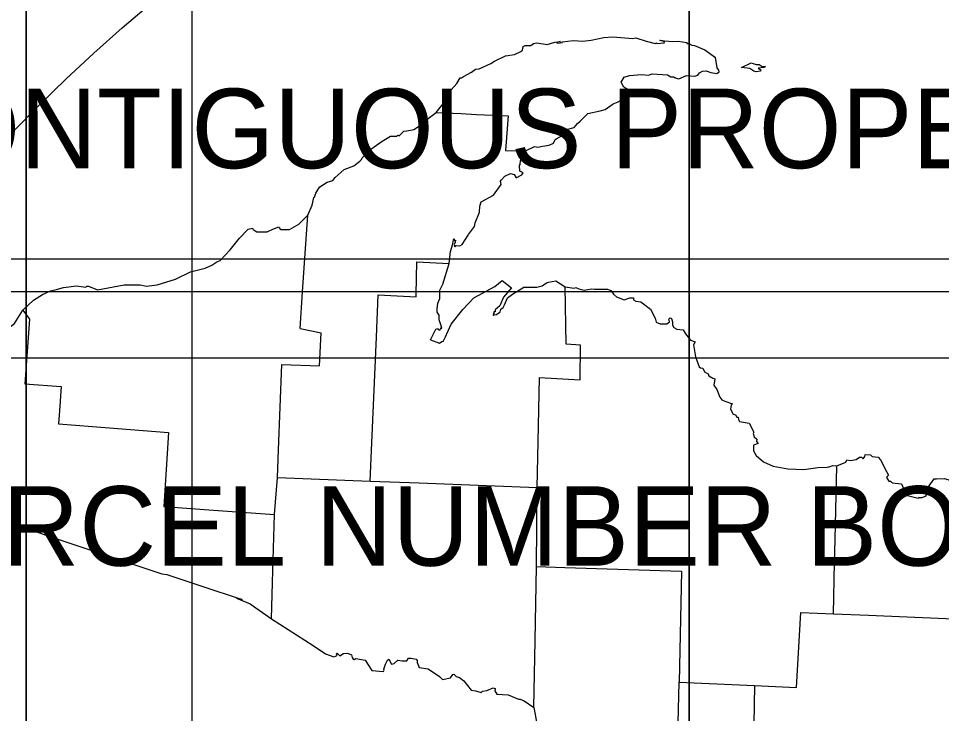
# Model space of a CAD drawing. Extents: x 2146475 to 2147951, y 2147003 to 2148003.
# Drawn here: x 2147652.9 to 2147708.6, y 2147835.5 to 2147877.5 of the extents above; entities that cross this region are included whole.
import ezdxf

# ---------------------------------------------------------------- set-up
doc = ezdxf.new("R2010")
doc.units = 0
for name, color, linetype in [('Sheet_Border_Prof3_Grid+Sta+EL_04_040+08_080', 7, 'Continuous'), ('Sheet_Border_Prof3_Grid+Sta+EL_10_100+20_200', 7, 'Continuous'), ('Sheet_Border_TitleSheet', 7, 'Continuous'), ('Sheet_Border_XS_Grid', 7, 'Continuous'), ('Sheet_Label_Misc_Wt1', 7, 'Continuous')]:
    doc.layers.add(name, color=color, linetype=linetype)

msp = doc.modelspace()

# ---------------------------------------------------------------- linework, layer by layer
at = {"layer": 'Sheet_Border_Prof3_Grid+Sta+EL_04_040+08_080'}
for p, q in [((2147663.414, 2147910.951), (2147663.414, 2147136.951)), ((2147813.414, 2147860.951), (2146613.414, 2147860.951))]:
    msp.add_line(p, q, dxfattribs=at)
at = {"layer": 'Sheet_Border_Prof3_Grid+Sta+EL_10_100+20_200'}
for p, q in [((2147653.414, 2147896.951), (2147653.414, 2147152.951)), ((2147693.414, 2147896.951), (2147693.414, 2147152.951)), ((2147813.414, 2147856.951), (2146613.414, 2147856.951))]:
    msp.add_line(p, q, dxfattribs=at)
at = {"layer": 'Sheet_Border_TitleSheet'}
for points in [[(2147684.853, 2147875.889), (2147685.305, 2147876.029), (2147685.662, 2147876.067), (2147685.411, 2147876.001), (2147685.495, 2147875.975), (2147685.781, 2147876.003), (2147685.756, 2147876.051), (2147686.433, 2147876.131), (2147687.006, 2147876.095), (2147687.501, 2147876.143), (2147688.271, 2147876.309)], [(2147688.271, 2147876.309), (2147688.813, 2147876.353), (2147690.02, 2147876.255), (2147690.21, 2147876.279), (2147690.817, 2147876.077)], [(2147690.817, 2147876.077), (2147691.358, 2147875.953), (2147691.448, 2147875.991), (2147691.452, 2147875.955), (2147691.921, 2147875.983), (2147691.884, 2147876.057), (2147691.641, 2147876.119), (2147691.709, 2147876.155), (2147691.934, 2147876.113), (2147692.42, 2147876.075), (2147692.749, 2147876.085), (2147693.287, 2147876.001), (2147693.269, 2147875.945), (2147693.394, 2147875.937), (2147693.574, 2147875.839), (2147693.738, 2147875.821), (2147694.364, 2147875.555), (2147695.007, 2147875.107)], [(2147682.336, 2147875.207), (2147682.877, 2147875.291), (2147683.258, 2147875.453), (2147683.364, 2147875.549), (2147683.399, 2147875.755), (2147683.525, 2147875.829), (2147683.861, 2147875.831), (2147684.021, 2147875.951), (2147684.225, 2147875.977), (2147684.853, 2147875.889)], [(2147678.151, 2147871.787), (2147678.731, 2147872.495), (2147678.902, 2147872.975), (2147679.406, 2147873.529), (2147679.596, 2147873.871), (2147679.687, 2147873.879), (2147679.8, 2147873.945), (2147680.283, 2147874.215), (2147680.518, 2147874.399), (2147680.752, 2147874.417), (2147681.445, 2147874.729), (2147681.673, 2147874.885), (2147682.336, 2147875.207)], [(2147690.024, 2147872.959), (2147689.47, 2147873.301), (2147689.318, 2147873.615), (2147689.488, 2147873.923), (2147689.819, 2147874.013), (2147690.535, 2147874.073), (2147690.957, 2147874.029), (2147691.194, 2147874.121), (2147692.12, 2147874.063), (2147692.318, 2147873.931), (2147692.487, 2147873.931), (2147692.573, 2147873.867), (2147692.804, 2147873.815), (2147693.267, 2147874.023), (2147693.753, 2147873.971), (2147693.939, 2147874.031), (2147694.049, 2147874.179), (2147694.215, 2147874.281), (2147694.453, 2147874.295), (2147694.732, 2147874.193), (2147695.081, 2147874.139), (2147695.228, 2147874.225), (2147695.215, 2147874.327), (2147695.113, 2147874.475), (2147695.007, 2147875.107)], [(2147696.582, 2147874.499), (2147697.158, 2147874.769), (2147697.467, 2147874.671), (2147697.634, 2147874.671), (2147697.826, 2147874.555), (2147698.033, 2147874.549), (2147697.935, 2147874.493), (2147697.59, 2147874.461), (2147697.735, 2147874.363), (2147697.721, 2147874.281), (2147697.47, 2147874.243), (2147697.314, 2147874.283), (2147697.074, 2147874.429), (2147696.582, 2147874.499)], [(2147683.539, 2147869.463), (2147684.081, 2147869.721), (2147684.294, 2147869.677), (2147684.577, 2147869.755), (2147684.97, 2147869.801), (2147685.232, 2147869.933), (2147685.325, 2147870.143), (2147685.435, 2147870.205), (2147685.758, 2147870.393), (2147685.828, 2147870.539), (2147686.105, 2147870.783), (2147686.483, 2147870.881), (2147686.683, 2147871.115), (2147686.847, 2147871.247), (2147687.303, 2147871.717), (2147688.058, 2147871.879), (2147688.357, 2147871.951), (2147688.843, 2147872.297), (2147689.144, 2147872.415), (2147689.42, 2147872.585), (2147690.024, 2147872.959)], [(2147672.61, 2147868.331), (2147673.193, 2147868.567), (2147673.55, 2147868.845), (2147673.638, 2147868.939), (2147673.68, 2147869.037), (2147674.061, 2147869.471), (2147674.895, 2147870.049), (2147675.405, 2147870.355), (2147675.77, 2147870.357), (2147675.845, 2147870.409), (2147675.924, 2147870.373), (2147676.21, 2147870.647), (2147676.386, 2147870.667), (2147676.807, 2147870.749), (2147677.147, 2147870.981), (2147677.434, 2147871.239), (2147678.151, 2147871.787)], [(2147678.151, 2147871.787), (2147679.664, 2147871.711)], [(2147679.664, 2147871.711), (2147680.586, 2147871.665)], [(2147680.586, 2147871.665), (2147682.493, 2147871.571), (2147682.333, 2147869.493), (2147683.539, 2147869.463)], [(2147681.602, 2147866.795), (2147682.069, 2147867.439), (2147682.042, 2147867.639), (2147682.073, 2147867.699), (2147682.29, 2147867.931), (2147682.633, 2147868.103), (2147682.849, 2147868.041), (2147682.984, 2147867.837), (2147683.327, 2147868.009), (2147683.411, 2147868.131), (2147683.193, 2147868.239), (2147683.176, 2147868.581), (2147683.229, 2147868.639), (2147683.249, 2147868.891), (2147683.539, 2147869.463)], [(2147670.401, 2147865.579), (2147670.673, 2147866.181), (2147670.765, 2147866.647), (2147670.817, 2147866.677), (2147670.896, 2147866.909), (2147671.013, 2147867.105), (2147671.126, 2147867.291), (2147671.584, 2147867.573), (2147671.924, 2147867.681), (2147672.062, 2147867.857), (2147672.61, 2147868.331)], [(2147678.942, 2147862.657), (2147679.011, 2147863.387), (2147679.153, 2147863.857), (2147679.198, 2147864.091), (2147679.243, 2147864.151), (2147679.267, 2147864.039), (2147679.319, 2147864.063), (2147679.301, 2147863.951), (2147679.24, 2147863.805), (2147679.275, 2147863.667), (2147679.364, 2147863.759), (2147679.574, 2147863.739), (2147679.713, 2147863.817), (2147680.078, 2147864.367), (2147680.101, 2147864.419), (2147680.471, 2147864.895), (2147680.503, 2147865.121), (2147680.767, 2147865.755), (2147680.781, 2147866.119), (2147680.858, 2147866.387), (2147681.602, 2147866.795)], [(2147666.288, 2147864.197), (2147666.814, 2147864.745), (2147667.059, 2147864.795), (2147667.103, 2147864.713), (2147667.339, 2147864.575), (2147667.957, 2147864.565), (2147668.293, 2147864.731), (2147668.65, 2147864.871), (2147668.676, 2147864.819), (2147668.757, 2147864.707), (2147669.307, 2147864.715), (2147669.865, 2147865.031), (2147670.401, 2147865.579)], [(2147670.093, 2147860.947), (2147670.401, 2147865.579)], [(2147664.217, 2147862.383), (2147664.624, 2147862.571), (2147664.923, 2147862.765), (2147665.119, 2147862.853), (2147665.427, 2147863.163), (2147665.711, 2147863.497), (2147666.288, 2147864.197)], [(2147676.955, 2147860.787), (2147676.991, 2147862.757), (2147678.942, 2147862.657)], [(2147677.805, 2147858.051), (2147678.14, 2147858.695), (2147678.236, 2147858.745), (2147678.264, 2147858.687), (2147678.374, 2147858.635), (2147678.445, 2147858.809), (2147678.45, 2147858.725), (2147678.499, 2147858.771), (2147678.343, 2147859.253), (2147678.332, 2147859.549), (2147678.217, 2147859.729), (2147678.204, 2147859.919), (2147678.261, 2147860.261), (2147678.375, 2147860.553), (2147678.368, 2147861.057), (2147678.563, 2147861.417), (2147678.942, 2147862.657)], [(2147657.711, 2147861.065), (2147659.329, 2147861.367), (2147660.298, 2147861.385), (2147660.677, 2147861.291), (2147661.306, 2147861.383), (2147662.413, 2147861.711), (2147663.335, 2147862.157), (2147664.217, 2147862.383)], [(2147680.426, 2147860.591), (2147681.69, 2147861.277), (2147682.139, 2147861.631), (2147682.689, 2147861.187)], [(2147683.443, 2147861.225), (2147684.221, 2147861.243), (2147684.551, 2147861.317), (2147684.816, 2147861.497), (2147684.932, 2147861.539), (2147685.368, 2147861.609), (2147685.935, 2147861.261)], [(2147653.214, 2147859.849), (2147653.86, 2147860.451), (2147654.394, 2147860.793), (2147654.877, 2147861.003), (2147655.16, 2147861.073), (2147655.668, 2147861.215), (2147656.455, 2147861.315), (2147657.02, 2147861.243), (2147657.069, 2147861.289), (2147657.169, 2147861.297), (2147657.711, 2147861.065)], [(2147682.689, 2147861.187), (2147682.212, 2147860.629), (2147681.986, 2147860.105), (2147681.708, 2147859.869), (2147681.704, 2147859.747), (2147681.674, 2147859.735), (2147681.616, 2147859.695), (2147681.673, 2147859.671), (2147681.6, 2147859.593), (2147681.619, 2147859.521), (2147681.641, 2147859.571), (2147681.789, 2147859.587), (2147682.023, 2147859.749), (2147682.048, 2147859.903), (2147682.202, 2147859.999), (2147682.282, 2147860.161), (2147682.447, 2147860.581), (2147682.751, 2147860.821), (2147683.443, 2147861.225)], [(2147684.315, 2147851.899), (2147684.397, 2147855.779), (2147686.844, 2147855.649), (2147686.864, 2147857.729), (2147686.004, 2147857.783), (2147685.935, 2147861.261)], [(2147685.935, 2147861.261), (2147686.477, 2147861.177), (2147686.572, 2147861.215), (2147686.752, 2147861.133), (2147687.081, 2147861.051), (2147687.533, 2147861.137), (2147687.705, 2147861.107), (2147688.492, 2147861.119), (2147688.683, 2147861.037), (2147688.851, 2147860.817), (2147689.027, 2147860.657), (2147689.493, 2147860.463), (2147689.848, 2147860.589), (2147690.051, 2147860.591), (2147690.057, 2147860.465), (2147690.201, 2147860.387), (2147690.498, 2147860.347), (2147691.093, 2147859.909)], [(2147669.947, 2147858.741), (2147670.093, 2147860.947)], [(2147674.546, 2147858.219), (2147674.657, 2147860.763), (2147676.952, 2147860.657)], [(2147676.952, 2147860.657), (2147676.955, 2147860.787)], [(2147677.805, 2147858.051), (2147678.346, 2147857.855), (2147678.489, 2147857.961), (2147678.601, 2147857.967), (2147678.586, 2147858.003), (2147678.694, 2147858.197), (2147679.063, 2147858.999), (2147679.765, 2147859.883), (2147680.426, 2147860.591)], [(2147691.093, 2147859.909), (2147691.369, 2147859.355), (2147691.435, 2147859.127), (2147691.676, 2147859.017), (2147692.079, 2147859.019), (2147692.223, 2147859.151), (2147692.19, 2147859.311), (2147692.266, 2147859.387), (2147692.355, 2147859.345), (2147692.422, 2147859.135), (2147692.418, 2147858.945), (2147692.486, 2147858.809), (2147692.679, 2147858.703), (2147693.062, 2147858.657), (2147693.205, 2147858.419), (2147693.504, 2147858.035), (2147693.772, 2147857.937), (2147693.689, 2147857.747), (2147693.808, 2147857.037)], [(2147643.219, 2147854.817), (2147643.873, 2147855.261), (2147644.411, 2147855.545), (2147645.101, 2147855.947), (2147645.27, 2147855.995), (2147645.631, 2147855.827), (2147645.917, 2147855.835), (2147646.68, 2147856.137), (2147647.755, 2147856.417), (2147648.166, 2147856.637), (2147649.023, 2147856.839), (2147649.551, 2147856.909), (2147650.182, 2147857.035), (2147650.41, 2147857.131), (2147651.219, 2147857.519), (2147651.529, 2147857.855), (2147651.75, 2147858.187), (2147651.89, 2147858.321), (2147652.236, 2147858.561), (2147652.469, 2147858.851), (2147652.704, 2147859.045), (2147653.214, 2147859.849)], [(2147653.214, 2147859.849), (2147653.615, 2147859.307), (2147653.328, 2147855.405), (2147655.519, 2147855.245), (2147655.415, 2147853.759)], [(2147668.639, 2147851.405), (2147668.843, 2147856.571), (2147671.102, 2147856.483), (2147671.214, 2147858.479)], [(2147669.947, 2147858.741), (2147671.214, 2147858.479)], [(2147674.27, 2147851.845), (2147674.546, 2147858.219)], [(2147693.808, 2147857.037), (2147694.02, 2147856.427), (2147694.106, 2147856.357), (2147694.246, 2147856.339), (2147694.354, 2147856.121), (2147694.567, 2147856.011), (2147694.606, 2147855.885), (2147694.852, 2147855.737), (2147694.971, 2147855.691), (2147694.901, 2147855.311), (2147695.086, 2147855.051), (2147695.269, 2147854.603), (2147695.39, 2147854.435), (2147695.566, 2147854.343), (2147696.031, 2147854.199), (2147695.963, 2147854.105), (2147695.917, 2147853.877), (2147696.081, 2147853.569), (2147696.208, 2147853.533), (2147696.296, 2147853.387), (2147696.379, 2147853.385), (2147696.401, 2147853.239), (2147696.466, 2147853.131), (2147697.047, 2147853.025)], [(2147655.415, 2147853.759), (2147655.361, 2147852.977), (2147657.407, 2147852.817)], [(2147657.407, 2147852.817), (2147662.008, 2147852.461), (2147661.714, 2147847.991), (2147664.723, 2147847.779)], [(2147697.047, 2147853.025), (2147697.318, 2147852.473), (2147697.284, 2147852.403), (2147697.351, 2147852.195), (2147697.493, 2147852.051), (2147697.478, 2147851.923), (2147697.583, 2147851.791), (2147697.308, 2147851.687), (2147697.297, 2147851.353), (2147697.461, 2147851.071), (2147697.909, 2147850.693), (2147698.493, 2147850.427), (2147699.38, 2147850.273), (2147700.345, 2147850.231), (2147701.185, 2147850.355)], [(2147674.17, 2147849.531), (2147674.27, 2147851.845)], [(2147684.256, 2147849.141), (2147684.315, 2147851.899)], [(2147668.574, 2147849.747), (2147668.639, 2147851.405)], [(2147702.323, 2147850.445), (2147702.865, 2147850.673), (2147702.933, 2147850.807), (2147703.158, 2147850.761), (2147703.497, 2147850.825), (2147703.7, 2147850.963), (2147703.809, 2147850.971), (2147703.92, 2147850.873), (2147704.027, 2147851.009), (2147704.046, 2147851.125), (2147704.363, 2147851.115), (2147704.465, 2147851.001), (2147704.815, 2147850.967), (2147704.971, 2147850.815), (2147705.326, 2147850.107), (2147705.441, 2147849.877), (2147705.361, 2147849.807), (2147705.335, 2147849.741), (2147705.477, 2147849.527), (2147705.56, 2147849.519), (2147705.675, 2147849.419), (2147706.242, 2147849.361)], [(2147701.831, 2147850.391), (2147701.876, 2147850.391), (2147702.084, 2147850.477), (2147702.323, 2147850.445)], [(2147702.227, 2147846.007), (2147702.323, 2147850.445)], [(2147701.185, 2147850.355), (2147701.755, 2147850.367)], [(2147701.755, 2147850.367), (2147701.831, 2147850.391)], [(2147668.404, 2147847.519), (2147668.574, 2147849.747)], [(2147668.574, 2147849.747), (2147674.17, 2147849.531)], [(2147674.17, 2147849.531), (2147677.127, 2147849.415)], [(2147677.127, 2147849.415), (2147684.256, 2147849.141)], [(2147706.242, 2147849.361), (2147706.474, 2147848.791), (2147706.588, 2147848.663), (2147707.233, 2147848.499), (2147707.283, 2147848.545), (2147707.484, 2147848.535), (2147707.724, 2147848.635), (2147707.85, 2147849.161), (2147708.21, 2147849.655), (2147708.339, 2147849.655), (2147708.812, 2147849.681), (2147709.032, 2147849.629), (2147709.247, 2147849.517), (2147709.329, 2147849.183), (2147709.493, 2147849.039), (2147709.671, 2147848.709), (2147709.806, 2147848.577), (2147710.355, 2147848.697)], [(2147684.205, 2147844.369), (2147684.256, 2147849.141)], [(2147648.229, 2147848.553), (2147651.33, 2147847.521), (2147651.92, 2147847.235), (2147654.661, 2147846.245)], [(2147664.723, 2147847.779), (2147668.404, 2147847.519)], [(2147668.277, 2147843.411), (2147668.404, 2147847.519)], [(2147654.661, 2147846.245), (2147661.603, 2147843.935), (2147661.904, 2147843.879), (2147664.004, 2147843.187)], [(2147702.197, 2147844.607), (2147702.227, 2147846.007)], [(2147684.119, 2147839.895), (2147684.205, 2147844.369)], [(2147684.205, 2147844.369), (2147685.919, 2147844.313)], [(2147685.919, 2147844.313), (2147692.949, 2147844.079), (2147692.813, 2147837.395)], [(2147702.13, 2147841.515), (2147702.197, 2147844.607)], [(2147664.004, 2147843.187), (2147666.436, 2147842.381), (2147666.102, 2147842.467), (2147666.921, 2147842.125), (2147668.211, 2147841.217)], [(2147668.211, 2147841.217), (2147668.277, 2147843.411)], [(2147697.355, 2147837.179), (2147699.903, 2147837.057), (2147700.161, 2147841.601)], [(2147700.161, 2147841.601), (2147702.13, 2147841.515)], [(2147702.13, 2147841.515), (2147704.247, 2147841.423)], [(2147668.211, 2147841.217), (2147670.723, 2147839.599)], [(2147704.247, 2147841.423), (2147711.251, 2147841.125)], [(2147684.047, 2147835.863), (2147684.119, 2147839.895)], [(2147670.723, 2147839.599), (2147671.478, 2147839.087)], [(2147671.478, 2147839.087), (2147671.986, 2147838.923), (2147672.17, 2147838.991), (2147672.14, 2147839.105), (2147672.178, 2147839.129), (2147672.342, 2147838.977), (2147672.567, 2147839.107), (2147672.808, 2147839.129), (2147673.049, 2147839.043), (2147673.081, 2147838.873), (2147673.141, 2147838.777), (2147673.208, 2147838.751), (2147673.302, 2147838.821), (2147673.861, 2147838.717)], [(2147673.861, 2147838.717), (2147674.277, 2147838.091)], [(2147674.277, 2147838.091), (2147674.97, 2147838.029), (2147675.018, 2147838.109), (2147675, 2147838.177), (2147675.094, 2147838.479), (2147675.209, 2147838.707), (2147675.293, 2147838.781), (2147675.462, 2147838.483), (2147675.624, 2147838.513), (2147675.832, 2147838.711), (2147676.091, 2147838.683), (2147676.388, 2147838.673), (2147676.491, 2147838.843), (2147676.643, 2147838.827), (2147676.939, 2147838.777), (2147677.003, 2147838.687), (2147677, 2147838.583), (2147677.131, 2147838.271), (2147677.678, 2147838.187)], [(2147677.678, 2147838.187), (2147678.35, 2147837.723), (2147678.526, 2147837.553), (2147678.634, 2147837.577), (2147679.02, 2147837.645), (2147679.153, 2147837.843), (2147679.22, 2147837.873), (2147679.365, 2147837.731), (2147679.561, 2147837.659), (2147679.815, 2147837.465), (2147680.257, 2147836.905)], [(2147680.257, 2147836.905), (2147680.528, 2147836.861), (2147680.86, 2147836.771), (2147680.953, 2147836.845), (2147681.202, 2147836.893), (2147681.582, 2147837.045), (2147681.716, 2147837.003), (2147681.7, 2147836.861), (2147681.814, 2147836.669), (2147682.498, 2147836.627)], [(2147691.379, 2147830.925), (2147691.437, 2147834.989), (2147692.762, 2147834.927), (2147692.813, 2147837.395)], [(2147692.813, 2147837.395), (2147697.355, 2147837.179)], [(2147697.355, 2147837.179), (2147697.33, 2147834.879), (2147698.213, 2147834.845), (2147698.11, 2147829.821)], [(2147682.498, 2147836.627), (2147683.122, 2147836.357), (2147683.221, 2147836.361), (2147683.462, 2147836.265), (2147684.047, 2147835.863)], [(2147684.047, 2147835.863), (2147684.162, 2147835.217), (2147684.22, 2147834.797), (2147684.55, 2147834.253)]]:
    msp.add_lwpolyline(points, dxfattribs=at)
msp.add_circle((2147721.414, 2147804.998), 95.071, dxfattribs=at)
at = {"layer": 'Sheet_Border_XS_Grid'}
for p, q in [((2147653.414, 2147142.951), (2147653.414, 2147902.951)), ((2147693.414, 2147142.951), (2147693.414, 2147902.951)), ((2146573.414, 2147862.951), (2147853.414, 2147862.951))]:
    msp.add_line(p, q, dxfattribs=at)

# ---------------------------------------------------------------- texts
at = {"layer": 'Sheet_Label_Misc_Wt1'}
for s, p in [('CONTIGUOUS PROPERTY SYMBOL', (2147643.414, 2147868.417)), ('PARCEL NUMBER BOX', (2147643.414, 2147844.417))]:
    msp.add_text(s, height=4.8, dxfattribs=at).set_placement(p)

doc.saveas('drawing.dxf')
